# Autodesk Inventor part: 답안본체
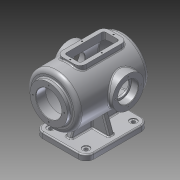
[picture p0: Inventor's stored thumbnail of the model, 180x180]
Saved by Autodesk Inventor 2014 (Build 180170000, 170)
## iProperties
Created: 2021-11
Part Number: 답안본체
Material: 알루미늄 6061
Document SubType Name: Modeling
Designer: kb542-12
Density: 2.71 g/cm^3
Appearance: 알루미늄 - 평지
Mass: 3554.29 g
Surface Area: 2405.16 cm^2
Volume: 1311.55 cm^3
Author: kb542-12
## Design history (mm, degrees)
sketch "스케치1"
  geometry: L1 (0, 0)-(210, 0); L2 (10, 65)-(10, 47.5); L3 (10, 47.5)-(0, 47.5); L4 (25, 55)-(25, 32.5); L5 (25, 32.5)-(0, 32.5); L6 (0, 32.5)-(0, 47.5); L7 (10, 65)-(185.993, 65); L8 (25, 55)-(181.239, 55); A1 r 100 centre (110, 0) between (210, 0) and (185.993, 65); A2 r 90 centre (110, 0) between (200, 0) and (181.239, 55)
  constraints: 16 end point, 4 point on circle, 3 perpendicular, 2 centre point, 2 point on line, 2 vertical alignment, 1 horizontal, 1 parallel, 1 vertical
  dimensions: "d0" = 210 distance of L1.start L1.end; "d6" = 65 diameter of L5 L1; "d7" = 95 diameter of L3 L1; "d8" = 25 distance of L4.end L5.end; "d9" = 10 distance between parallel lines of L6 L2; "d15" = 100 radius of A1; "d18" = 130 diameter of L7 L1; "d20" = 10 radial gap between concentric circles of A1 A2; "d23" = 110 diameter of L8 L1
revolve "회전1" sketch "스케치1" stored, may be unused: angle "d24" = 90 deg
node "작업 평면1"
sketch "스케치2"
  geometry: L1 (65, 30)-(155, 30); L2 (170, 15)-(170, -15); L3 (155, -30)-(65, -30); L4 (50, -15)-(50, 15); L5 (155, 20)-(65, 20); L6 (60, 15)-(60, -15); L7 (65, -20)-(155, -20); L8 (160, -15)-(160, 15); L9 (55, 25)-(165, 25); L10 (165, 25)-(165, -25); L11 (165, -25)-(55, -25); L12 (55, -25)-(55, 25); A1 r 15 centre (65, 15) between (65, 30) and (50, 15); A2 r 15 centre (155, 15) between (170, 15) and (155, 30); A3 r 15 centre (155, -15) between (155, -30) and (170, -15); A4 r 15 centre (65, -15) between (50, -15) and (65, -30); A5 r 5 centre (65, 15) between (65, 20) and (60, 15); A6 r 5 centre (65, -15) between (60, -15) and (65, -20); A7 r 5 centre (155, -15) between (155, -20) and (160, -15); A8 r 5 centre (155, 15) between (160, 15) and (155, 20); 14 further points
  constraints: 24 end point, 16 point on circle, 10 midpoint, 8 centre point, 8 tangent, 6 parallel, 6 point on line, 4 coincident, 3 equal radius, 3 horizontal alignment, 3 perpendicular, 2 horizontal, 7 other
  dimensions: "d26" = 120 distance of point (50, 30) point (170, 30); "d27" = 60 distance of point (50, -30) point (50, 30); "d28" = 50 distance from line of point (0, 0) L4; "d29" = 15 radius of A1; "d30" = 10 distance between parallel lines of L1 L5; "d31" = 50 distance of point (110, -25) point (110, 25); "d32" = 110 distance of point (165, 0) point (55, 0); "d33" = 5 distance of point (50, 0) point (55, 0)
extrude "돌출1" join sketch "스케치2" stored distance "d34" = 10; taper "d35" = 0 deg
hole "구멍1" sketch "스케치2" diameter "d36" = 3.242; stored, may be unused: countersink angle "d40" = 90 deg, drill point angle "d42" = 118 deg; dims "d37" = 9, "d38" = 4, "d39" = 2, "d41" = 11
node "작업 평면2"
sketch "스케치3"
  geometry: C1 r 40 at (127, 0); 1 further point
  constraints: 1 centre point, 1 horizontal alignment
  dimensions: "d44" = 80 diameter of C1; "d45" = 127 distance of point (0, 0) C1.centre
extrude "돌출2" join sketch "스케치3" stored distance "d46" = 10; taper "d47" = 0 deg
hole "구멍2" diameter "d50" = 42; stored, may be unused: countersink angle "d54" = 90 deg, drill point angle "d56" = 118 deg; dims "d48" = 10, "d49" = 10, "d51" = 9, "d52" = 52, "d53" = 18, "d55" = 11
sketch "스케치4"
  geometry: C1 r 40 at (127, 0) reference; A1 r 32.5 centre (127, 0) between (127, 32.5) and (127, -32.5); 3 further points
  constraints: 4 point on circle, 2 horizontal alignment, 2 vertical alignment, 1 centre point, 1 concentric
  dimensions: "d57" = 65 diameter of A1
hole "구멍3" sketch "스케치4" at (127, 32.5), (127, -32.5), (94.5, 0), (159.5, 0) diameter "d58" = 3.242; stored, may be unused: countersink angle "d62" = 90 deg, drill point angle "d64" = 118 deg; dims "d59" = 11, "d60" = 52, "d61" = 18, "d63" = 13
extrude "돌출3" cut sketch "스케치2" stored distance "d65" = 10; taper "d66" = 0 deg
node "작업 평면3"
sketch "스케치5"
  geometry: L1 (-170, 65)-(-50, 65); L2 (-30, 45)-(-30, -45); L3 (-50, -65)-(-170, -65); L4 (-190, -45)-(-190, 45); C1 r 4.5 at (-170, 45); C2 r 4.5 at (-50, 45); C3 r 4.5 at (-170, -45); C4 r 4.5 at (-50, -45); A1 r 20 centre (-170, 45) between (-170, 65) and (-190, 45); A2 r 20 centre (-50, 45) between (-30, 45) and (-50, 65); A3 r 20 centre (-50, -45) between (-50, -65) and (-30, -45); A4 r 20 centre (-170, -45) between (-190, -45) and (-170, -65); 5 further points
  constraints: 8 centre point, 8 end point, 8 point on circle, 8 tangent, 6 equal radius, 6 point on line, 4 coincident, 2 parallel, 1 horizontal, 1 horizontal alignment, 1 midpoint, 1 perpendicular
  dimensions: "d68" = 160 distance of point (-190, 65) point (-30, 65); "d69" = 130 distance of point (-30, 65) point (-30, -65); "d70" = 30 distance from line of point (0, 0) L2; "d71" = 20 radius of A1; "d72" = 9 diameter of C1
extrude "돌출5" join sketch "스케치5" distance "d75" = 14; taper "d76" = 0 deg
sketch "스케치7"
  geometry: A1 r 20 centre (50, 45) between (50, 65) and (30, 45) reference; A2 r 20 centre (50, -45) between (30, -45) and (50, -65) reference; A3 r 20 centre (170, -45) between (170, -65) and (190, -45) reference; A4 r 20 centre (170, 45) between (190, 45) and (170, 65) reference; 5 further points
  constraints: 4 coincident
hole "구멍4" sketch "스케치7" at (50, 45), (170, 45), (170, -45), (50, -45) diameter "d82" = 18; stored, may be unused: countersink angle "d86" = 90 deg, drill point angle "d88" = 0 deg; dims "d83" = 11, "d84" = 52, "d85" = 18, "d87" = 2
node "작업 평면4"
sketch "스케치9"
  geometry: L1 (0, -14)-(90, -14) reference; L2 (78.809, -58.485)-(95, -14); L3 (-5, -14)-(11.191, -58.485); L4 (45, -14)-(45, -114); L5 (95, -14)-(-5, -14); L6 (99, -14)-(81, -14) reference; A1 r 65 centre (45, -114) between (78.809, -58.485) and (11.191, -58.485) reference; A2 r 65 centre (45, -114) between (78.809, -58.485) and (11.191, -58.485); 2 further points
  constraints: 8 end point, 4 point on circle, 2 point on line, 1 centre point, 1 collinear, 1 concentric, 1 midpoint, 1 perpendicular, 1 vertical alignment, 1 other
  dimensions: "d98" = 110 deg angle of L6 L2; "d99" = 100 distance of L3.start L2.end
extrude "돌출6" join sketch "스케치9" stored distance "d100" = 14; taper "d101" = 0 deg
sketch "스케치8"
  geometry: L1 (10, -65)-(10, 65) reference; L2 (185.993, -65)-(185.993, 65) reference; L3 (65, -57.663)-(155, -57.663) reference; L4 (170, -63.246)-(170, -63.246) reference; L5 (155, -57.663)-(65, -57.663) reference; L6 (50, -63.246)-(50, -63.246) reference; L7 (30, 114)-(30, 100) reference; L8 (0, -47.5)-(0, 47.5) reference; L9 (30, 100)-(50, 100) reference; L10 (170, 100)-(157.261, 65); L11 (181.239, 55)-(25, 55) reference; L12 (10, 65)-(185.993, 65) reference; L13 (50, 100)-(170, 100) reference; L14 (110, 100)-(110, 65); 3 further points
  constraints: 4 end point, 3 point on line, 1 midpoint, 1 perpendicular, 6 other
  dimensions: "d102" = 110 deg angle of L9 L10; "d104" = 60 distance from line of L14 L10.start (derived)
feature "리브1" sketch "스케치8" dims "d105" = 1, "d106" = 14, "d107" = 0, "d108" = 0, "d109" = 1, "d110" = 1
sketch "스케치10"
  geometry: C1 r 32.5 at (0, 0) reference; A1 r 40 centre (0, 0) between (0, 40) and (0, -40); 2 further points
  constraints: 4 point on circle, 2 horizontal alignment, 2 vertical alignment, 1 centre point, 1 coincident
  dimensions: "d111" = 80 diameter of A1
hole "구멍5" sketch "스케치10" at (0, 40), (0, -40), (-40, 0), (40, 0) diameter "d112" = 3.242; stored, may be unused: countersink angle "d116" = 90 deg, drill point angle "d118" = 118 deg; dims "d113" = 11, "d114" = 52, "d115" = 18, "d117" = 13
fillet "모깎기1" dims "d119" = 10
fillet "모깎기3" dims "d121" = 3
fillet "모깎기2" dims "d120" = 3
fillet "모깎기4" dims "d122" = 3
chamfer "모따기1" distance "d123" = 1; stored, may be unused: second distance "d124" = 2, angle "d125" = 45 deg
fillet "모깎기5" dims "d126" = 0.3
node "솔리드1"
mirror "대칭1"
mirror "대칭2"
node "투영된 루프1"
other parameters: "d43" = 75, "d67" = 114
